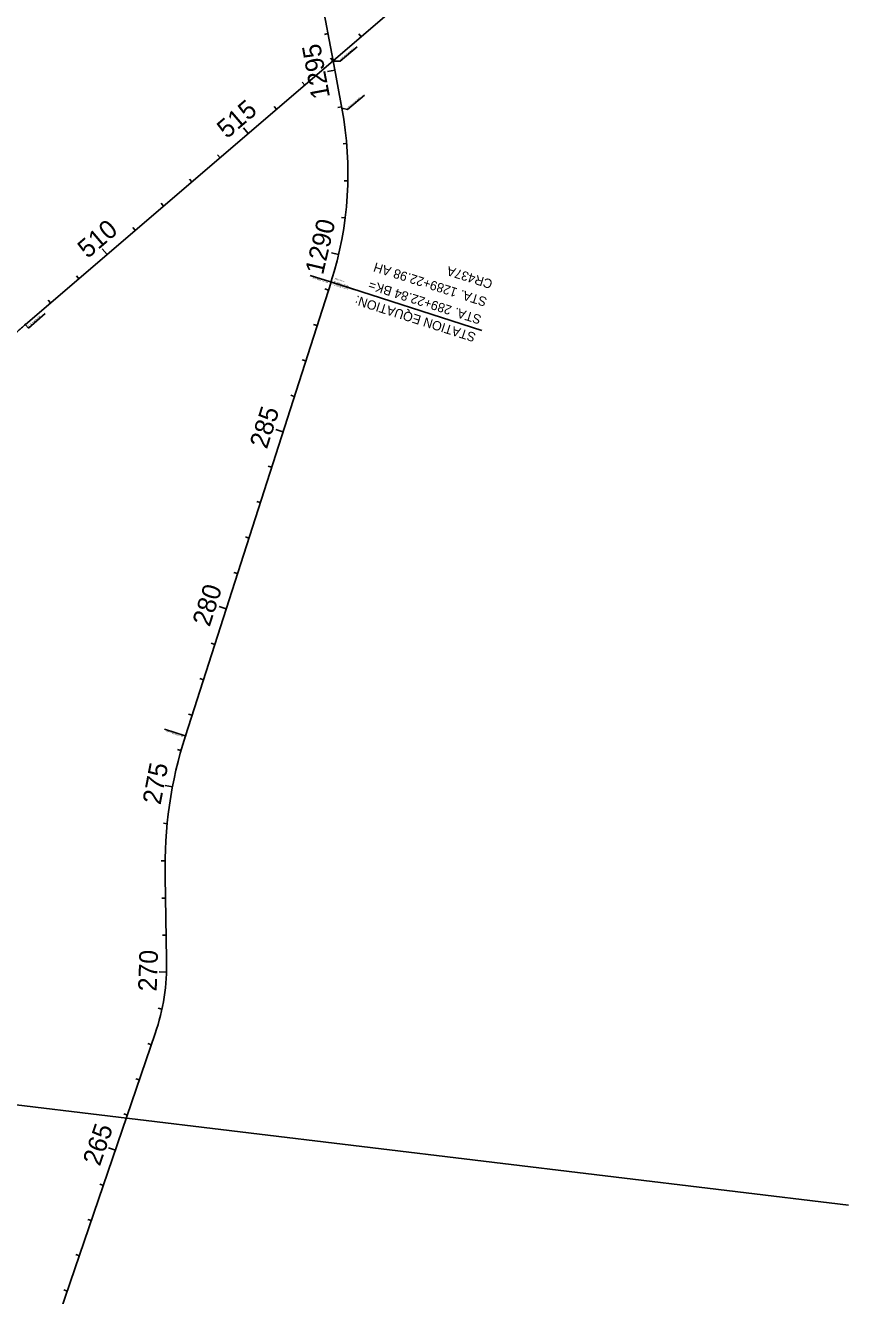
# Model space of a CAD drawing. Extents: x 448091 to 665917, y 1461380 to 1587607.
# Drawn here: x 482797 to 485011, y 1565305 to 1568719 of the extents above; entities that cross this region are included whole.
import ezdxf

# ---------------------------------------------------------------- set-up
doc = ezdxf.new("R2010")
doc.units = 0
for name, color, linetype in [('Attenuator_ep', 7, 'Continuous'), ('AttenuatorTM', 7, 'Continuous'), ('BarrierWall_ep', 7, 'Continuous'), ('BLSurveyCntrl_ep', 7, 'Continuous'), ('BLSurveyField_ep', 7, 'Continuous'), ('BLSurveySymbl_ep', 7, 'Continuous'), ('BoxCulvert', 7, 'Continuous')]:
    doc.layers.add(name, color=color, linetype=linetype)

msp = doc.modelspace()

# ---------------------------------------------------------------- linework, layer by layer
at = {"layer": 'Attenuator_ep'}
msp.add_line((483618, 1568029.5), (484024.2, 1567899.1), dxfattribs=at)
msp.add_circle((483618.8, 1568029.3), 0.8, dxfattribs=at)
at = {"layer": 'AttenuatorTM'}
for p, q in [((483643.6, 1568622.9), (483689.1, 1568662)), ((483643.6, 1568622.9), (483625, 1568623.4)), ((483663.1, 1568493), (483708.7, 1568532)), ((483663.1, 1568493), (483648.2, 1568496.5)), ((483617.8, 1568029.6), (483562.6, 1568047.3)), ((483619.7, 1568028.9), (483681, 1568009.3)), ((482804.9, 1567905.6), (482850.4, 1567944.6)), ((482797.5, 1567914.3), (482804.9, 1567905.6)), ((483226.2, 1566809.5), (483171.2, 1566827.1))]:
    msp.add_line(p, q, dxfattribs=at)
for centre in [(483624.3, 1568624.1), (483648.2, 1568496.5), (483618.8, 1568029.3), (482796.8, 1567915), (483227.2, 1566809.1)]:
    msp.add_circle(centre, 1, dxfattribs=at)
at = {"layer": 'BarrierWall_ep'}
msp.add_line((478564.6, 1566324.5), (485011, 1565547.4), dxfattribs=at)
at = {"layer": 'BLSurveyCntrl_ep'}
for p, q in [((483624.3, 1568624.1), (483593.4, 1568789.7)), ((483648.2, 1568496.5), (483624.3, 1568624.1)), ((483227.2, 1566809.1), (483618.8, 1568029.3)), ((483176.4, 1566207.7), (483172.7, 1566431.6)), ((482832.4, 1565090.7), (483145.9, 1566008.9))]:
    msp.add_line(p, q, dxfattribs=at)
for centre, radius, start, end in [((482709.5, 1568321.1), 954.9, 342.2071, 10.5871), ((484318.3, 1566458.9), 1145.9, 162.2031, 181.3656), ((482603.6, 1566194), 573, 341.1489, 1.3656)]:
    msp.add_arc(centre, radius, start, end, dxfattribs=at)
at = {"layer": 'BLSurveyField_ep'}
for p, q in [((483610.7, 1568697.1), (483600.9, 1568695.2)), ((483629.1, 1568598.8), (483609.4, 1568595.1)), ((483647.4, 1568500.5), (483637.6, 1568498.6)), ((483661, 1568401.4), (483651.1, 1568400.6)), ((483664.2, 1568301.5), (483654.2, 1568301.7)), ((483657, 1568201.8), (483647, 1568203.1)), ((483639.3, 1568103.5), (483619.8, 1568108)), ((483611.8, 1568007.5), (483602.3, 1568010.6)), ((483581.2, 1567912.3), (483571.7, 1567915.3)), ((483550.7, 1567817.1), (483541.1, 1567820.1)), ((483520.1, 1567721.9), (483510.6, 1567724.9)), ((483489.5, 1567626.6), (483470.5, 1567632.8)), ((483459, 1567531.4), (483449.5, 1567534.5)), ((483428.4, 1567436.2), (483418.9, 1567439.3)), ((483397.9, 1567341), (483388.4, 1567344)), ((483367.3, 1567245.8), (483357.8, 1567248.8)), ((483336.8, 1567150.6), (483317.7, 1567156.7)), ((483306.2, 1567055.3), (483296.7, 1567058.4)), ((483275.6, 1566960.1), (483266.1, 1566963.2)), ((483245.1, 1566864.9), (483235.6, 1566868)), ((483215.3, 1566769.5), (483205.6, 1566772.2)), ((483192.4, 1566672.2), (483172.7, 1566675.9)), ((483178.1, 1566573.2), (483168.1, 1566574.2)), ((483172.4, 1566473.4), (483162.4, 1566473.6)), ((483173.7, 1566373.4), (483163.7, 1566373.2)), ((483175.3, 1566273.5), (483165.3, 1566273.2)), ((483176.3, 1566174.1), (483156.3, 1566174.8)), ((483164.1, 1566075), (483154.3, 1566077)), ((483135.7, 1565979.1), (483126.3, 1565982.4)), ((483103.4, 1565884.5), (483094, 1565887.7)), ((483071.1, 1565789.9), (483061.6, 1565793.1)), ((483038.8, 1565695.2), (483019.9, 1565701.7)), ((483006.5, 1565600.6), (482997, 1565603.8)), ((482974.2, 1565506), (482964.7, 1565509.2)), ((482941.9, 1565411.3), (482932.4, 1565414.6)), ((482909.6, 1565316.7), (482900.1, 1565319.9))]:
    msp.add_line(p, q, dxfattribs=at)
at = {"layer": 'BoxCulvert'}
for p, q in [((482796.8, 1567915), (484539.7, 1569408.5)), ((483700, 1568688.9), (483693.5, 1568696.5)), ((483624, 1568623.9), (483617.5, 1568631.5)), ((483548.1, 1568558.8), (483541.6, 1568566.4)), ((483472.2, 1568493.7), (483465.7, 1568501.3)), ((483396.2, 1568428.7), (483383.2, 1568443.8)), ((483320.3, 1568363.6), (483313.8, 1568371.2)), ((483244.4, 1568298.5), (483237.8, 1568306.1)), ((483168.4, 1568233.5), (483161.9, 1568241.1)), ((483092.5, 1568168.4), (483086, 1568176)), ((483016.5, 1568103.3), (483003.5, 1568118.5)), ((482940.6, 1568038.3), (482934.1, 1568045.9)), ((482864.7, 1567973.2), (482858.2, 1567980.8))]:
    msp.add_line(p, q, dxfattribs=at)
msp.add_spline([(482796.8, 1567915), (482792.7, 1567911.5), (482788.6, 1567908), (482784.5, 1567904.5), (482780.4, 1567901), (482776.3, 1567897.5), (482772.2, 1567893.9), (482768.1, 1567890.4), (482764, 1567886.9), (482759.9, 1567883.4), (482755.8, 1567879.9), (482751.7, 1567876.3), (482747.6, 1567872.8), (482743.5, 1567869.3), (482739.4, 1567865.8), (482735.3, 1567862.2), (482731.2, 1567858.7), (482727.1, 1567855.2), (482723, 1567851.6), (482718.9, 1567848.1), (482714.8, 1567844.6), (482710.8, 1567841), (482706.7, 1567837.5), (482702.6, 1567833.9), (482698.5, 1567830.4), (482694.4, 1567826.8), (482690.4, 1567823.3), (482686.3, 1567819.7), (482682.2, 1567816.2), (482678.1, 1567812.6), (482674.1, 1567809.1), (482670, 1567805.5), (482666, 1567801.9), (482661.9, 1567798.4), (482657.8, 1567794.8), (482653.8, 1567791.2), (482649.7, 1567787.6), (482645.7, 1567784), (482641.7, 1567780.4), (482637.6, 1567776.9), (482633.6, 1567773.3), (482629.6, 1567769.7), (482625.5, 1567766), (482621.5, 1567762.4), (482617.5, 1567758.8), (482613.5, 1567755.2), (482609.5, 1567751.6), (482605.5, 1567747.9), (482601.5, 1567744.3), (482597.5, 1567740.7), (482593.5, 1567737), (482589.5, 1567733.4), (482585.5, 1567729.7), (482581.5, 1567726.1), (482577.5, 1567722.4), (482573.6, 1567718.7), (482569.6, 1567715.1), (482565.7, 1567711.4), (482561.7, 1567707.7), (482557.8, 1567704), (482553.8, 1567700.3), (482549.9, 1567696.6), (482545.9, 1567692.9), (482542, 1567689.2), (482538.1, 1567685.4), (482534.2, 1567681.7), (482530.3, 1567678), (482526.4, 1567674.2), (482522.5, 1567670.5), (482518.6, 1567666.7), (482514.7, 1567663), (482510.9, 1567659.2), (482507, 1567655.4), (482503.1, 1567651.6), (482499.3, 1567647.8)], degree=3, dxfattribs=at)

# ---------------------------------------------------------------- texts
at = {"layer": 'Attenuator_ep'}
for s, p in [('STA. 1289+22.98 AH', (484040.4, 1567986.5)), ('CR437A', (484055.6, 1568034.1)), ('STA. 289+22.84 BK=', (484025.3, 1567938.8)), ('STATION EQUATION:', (484010.2, 1567891.2))]:
    msp.add_text(s, height=25, rotation=162.3814, dxfattribs=at).set_placement(p)
at = {"layer": 'AttenuatorTM'}
for s, rotation, p in [('POT STA 1295+25.79', 40.3155, (483645.8, 1568626.1)), ('PT STA 1293+95.98', 40.4708, (483663.9, 1568495.2)), ('PC STA 1289+22.98', 162.2071, (483611.6, 1568029.7)), ('EQUATION:', 342.2071, (483628.6, 1568037.1)), ('Sta 289+22.84 BK = ', 342.2071, (483622.9, 1568021.5)), ('Sta 1289+22.98 AH', 342.2071, (483625.5, 1568028.9)), ('ST STA. 507+10.64', 40.5919, (482805.2, 1567908.8)), ('POT STA 276+41.44', 162.2071, (483220, 1566809.6))]:
    msp.add_text(s, height=3.5, rotation=rotation, dxfattribs=at).set_placement(p)
at = {"layer": 'BLSurveySymbl_ep'}
for s, rotation, p in [('1295', 100.587, (483616.4, 1568526.7)), ('1290', 76.8283, (483597.2, 1568046.8)), ('285', 72.2071, (483446.3, 1567578.5)), ('280', 72.2071, (483292.3, 1567100.5)), ('275', 79.1681, (483160.3, 1566622.2)), ('270', 88.0081, (483149.8, 1566121.5)), ('265', 71.1489, (482997, 1565650.4))]:
    msp.add_text(s, height=50, rotation=rotation, dxfattribs=at).set_placement(p)
at = {"layer": 'BoxCulvert'}
for s, p in [('515', (483338.9, 1568412.9)), ('510', (482964.2, 1568090.8))]:
    msp.add_text(s, height=50, rotation=40.5919, dxfattribs=at).set_placement(p)

doc.saveas('drawing.dxf')
